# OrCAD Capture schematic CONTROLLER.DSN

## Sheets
1 Analog + Header: size A; title: USB Game Controller
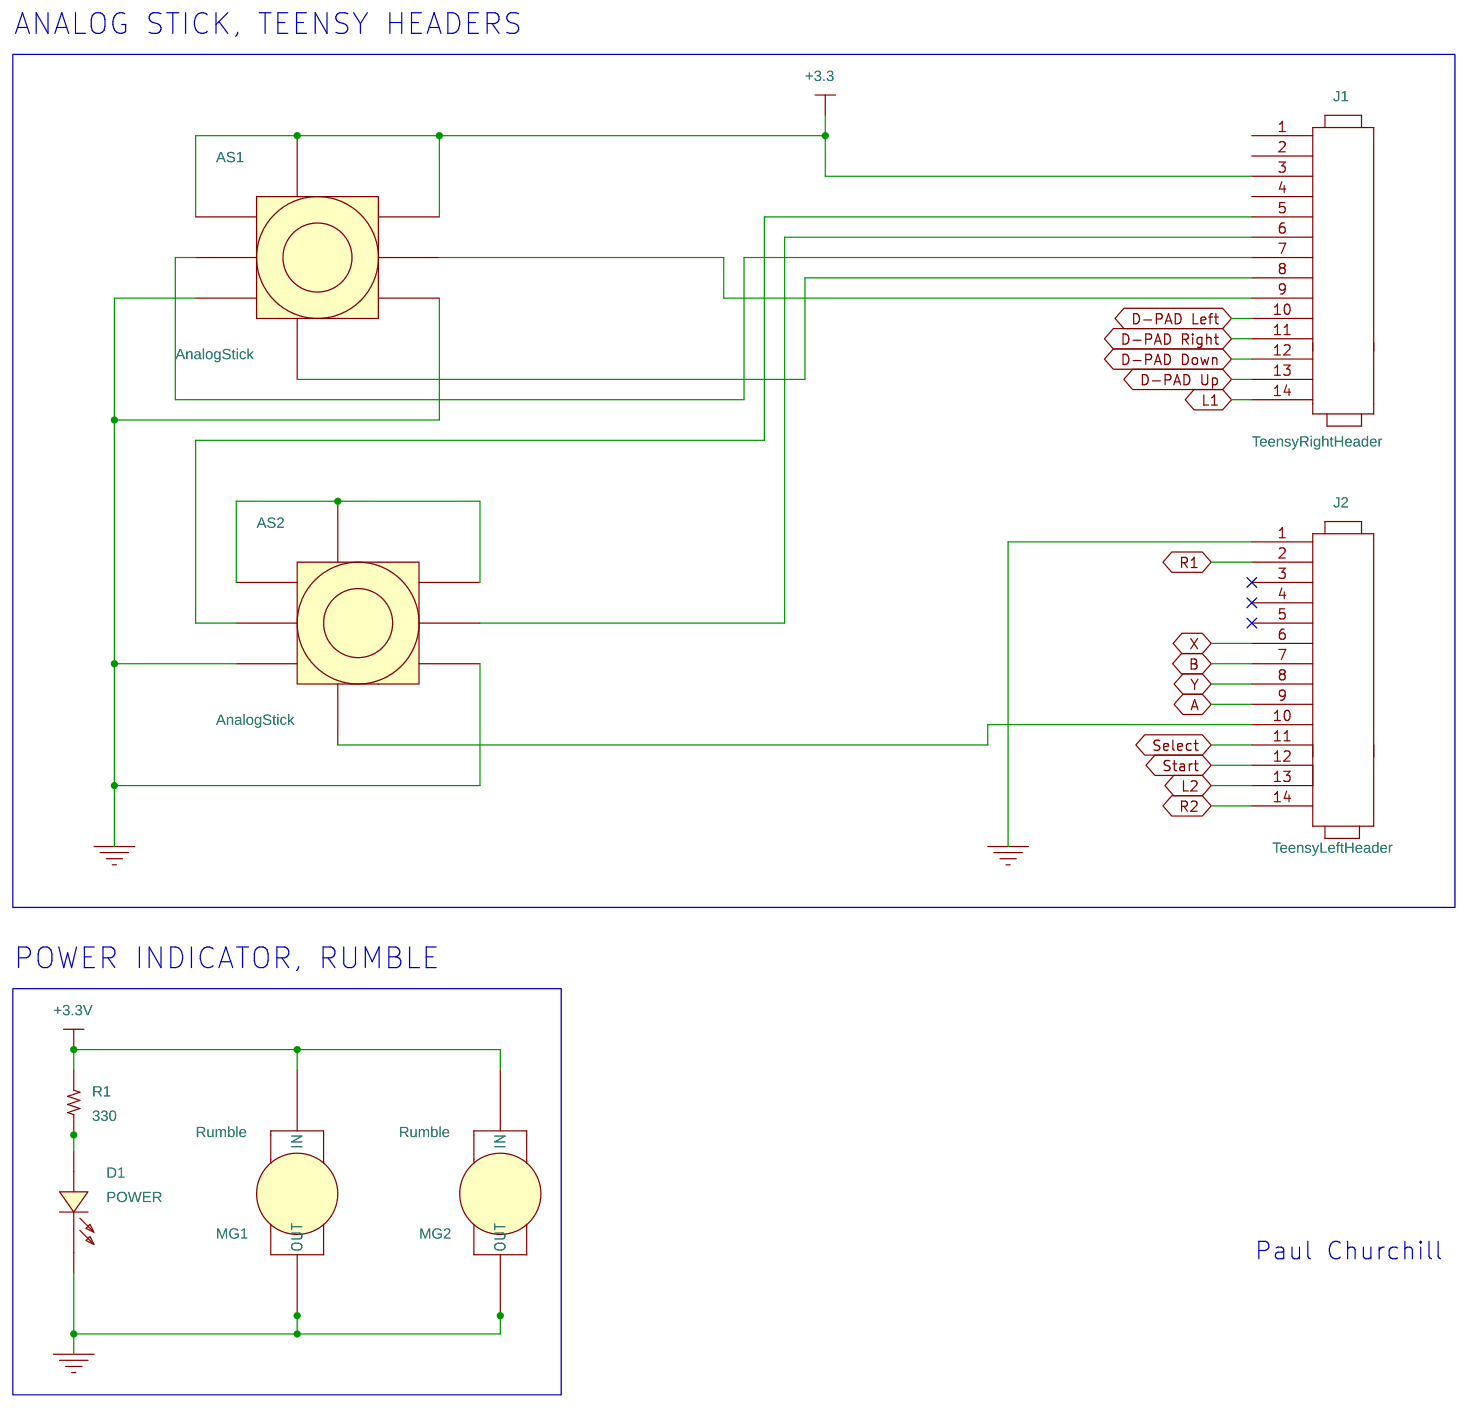
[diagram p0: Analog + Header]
2 Button: size A
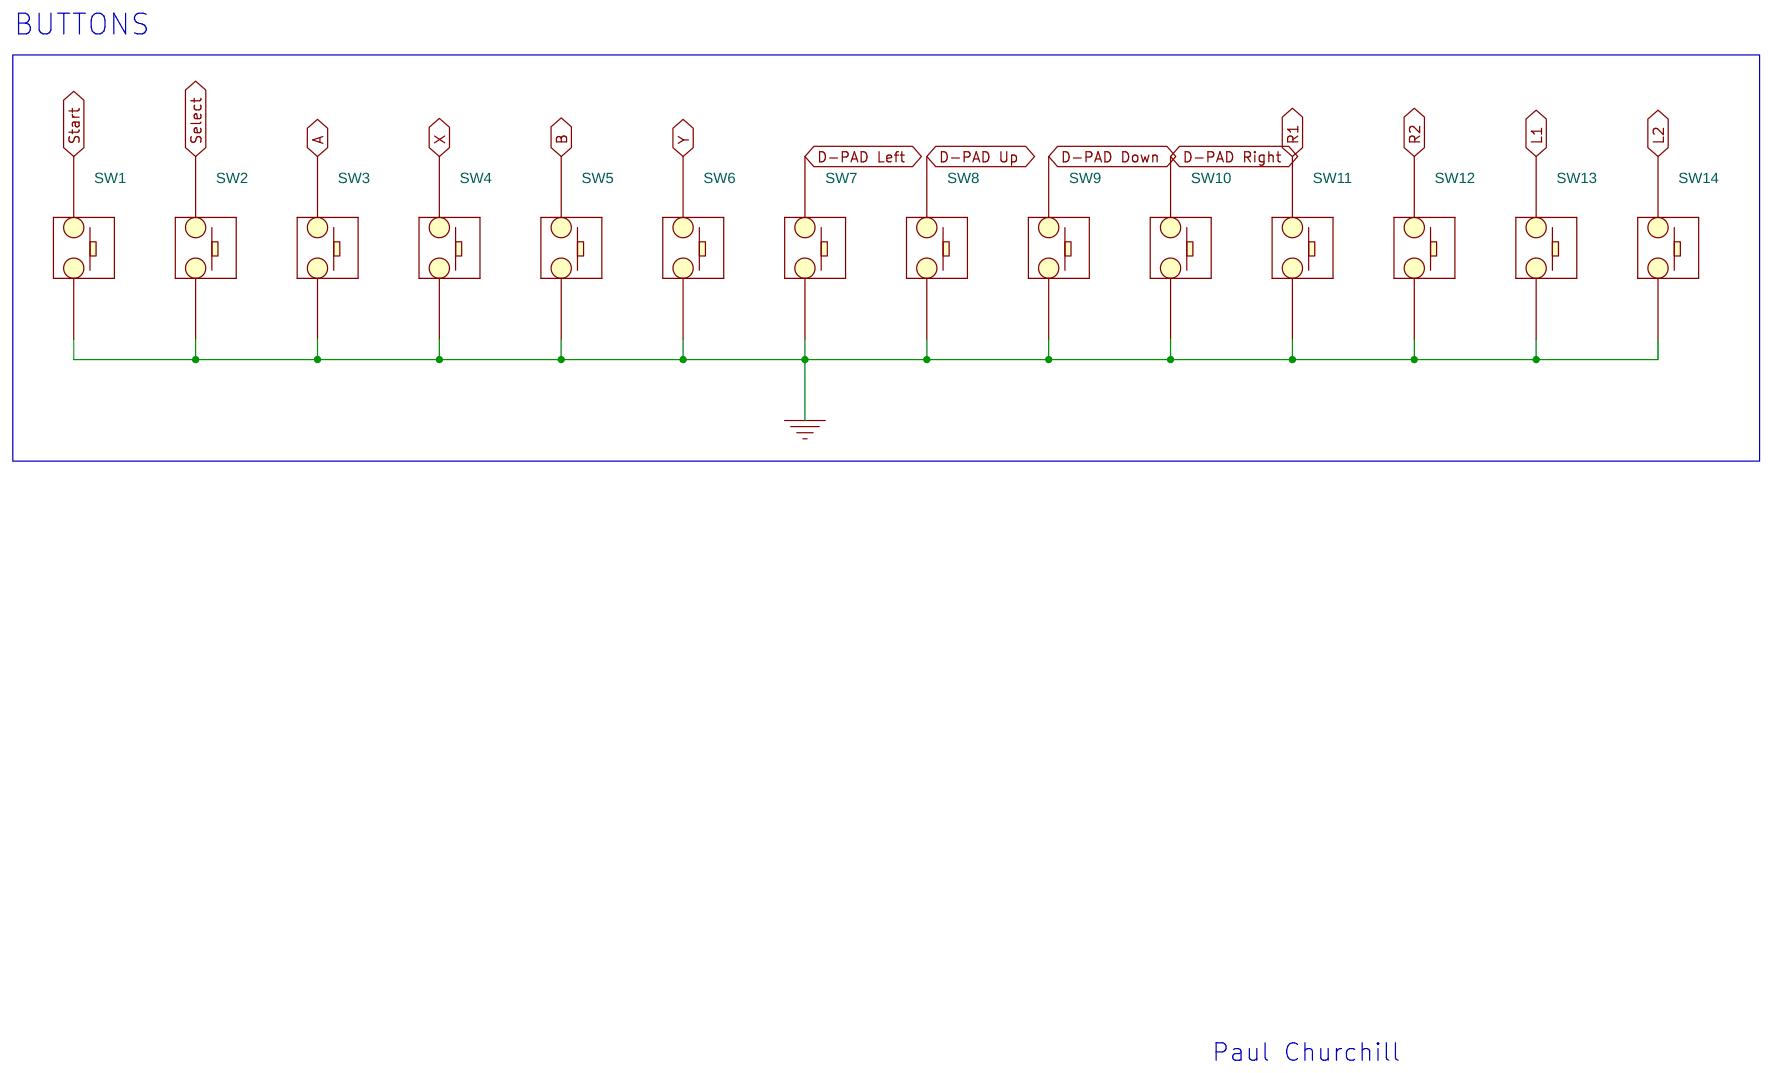
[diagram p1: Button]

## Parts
sheet Analog + Header
AS1  AnalogStick  [AnalogStick]
AS2  AnalogStick  [AnalogStick]
D1  POWER  [LED]
J1  TeensyRightHeader  [Header10]
J2  TeensyLeftHeader  [Header10]
MG1  Rumble  [Header2]
MG2  Rumble  [Header2]
R1  330  [RESISTOR]
sheet Button
SW1  Keyswitch  [Keyswitch]
SW2  Keyswitch  [Keyswitch]
SW3  Keyswitch  [Keyswitch]
SW4  Keyswitch  [Keyswitch]
SW5  Keyswitch  [Keyswitch]
SW6  Keyswitch  [Keyswitch]
SW7  Keyswitch  [Keyswitch]
SW8  Keyswitch  [Keyswitch]
SW9  Keyswitch  [Keyswitch]
SW10  Keyswitch  [Keyswitch]
SW11  Keyswitch  [Keyswitch]
SW12  Keyswitch  [Keyswitch]
SW13  Keyswitch  [Keyswitch]
SW14  Keyswitch  [Keyswitch]

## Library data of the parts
AS1 AS2 = AnalogStick
D1 = LED
J1 = TeensyRightHeader
J2 = TeensyLeftHeader
MG1 MG2 = Rumble
R1 = Resistor
SW1-SW14 = Keyswitch

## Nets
+3.3v: MG1.1(IN) MG2.1(IN) R1.2
GND: AS1.3 AS1.6 AS2.3 AS2.6 D1.1(CATHODE) J2.1(GND) MG1.2(OUT) MG2.2(OUT) SW1.2 SW2.2 SW3.2 SW4.2 SW5.2 SW6.2 SW7.2 SW8.2 SW9.2 SW10.2 SW11.2 SW12.2 SW13.2 SW14.2
+3.3: AS1.1 AS1.4 AS1.7 J1.3(3.3V)
A: J2.9 SW3.1
B: J2.7 SW5.1
D-PAD Down: J1.12(21) SW9.1
D-PAD Left: J1.10(19) SW7.1
D-PAD Right: J1.11(20) SW10.1
D-PAD Up: J1.13(22) SW8.1
L1: J1.14(23) SW13.1
L2: J2.13(A10) SW14.1
R1: J2.2 SW11.1
R2: J2.14(A11) SW12.1
Select: J2.11 SW2.1
Start: J2.12 SW1.1
X: J2.6 SW4.1
Y: J2.8 SW6.1
N24817: D1.2(ANODE) R1.1
N49615: AS2.2 J1.5(14)
N49627: AS1.2 J1.7(16)
N49814: AS2.1 AS2.4 AS2.7
N50813: AS2.5 J1.6(15)
N50846: AS1.5 J1.9(18)
N50861: AS1.9 J1.8(17)
N50873: AS2.9 J2.10

Not connected (* = marked no-connect by the designer): AS1 8 10; AS2 8 10; J1 1(Vin) 2(AGnd) 4(13); J2 3* 4* 5*

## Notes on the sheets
sheet 1
- ANALOG STICK, TEENSY HEADERS
- POWER INDICATOR, RUMBLE
- Paul Churchill
sheet 2
- BUTTONS
- Paul Churchill
